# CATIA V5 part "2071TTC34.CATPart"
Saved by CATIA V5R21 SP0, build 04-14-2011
Part number: 2071TTC34
Bounding box of the stored display mesh (mm): x -14 to 14, y 0 to 1000, z -22.5 to 18.5
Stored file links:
  C:\Users\ALI OZGUN\Desktop\alhan\PROFILLER\2071TTC34.CATPart
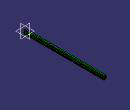
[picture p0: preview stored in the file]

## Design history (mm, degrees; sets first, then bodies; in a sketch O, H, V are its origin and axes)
Body1 (main body)
  Sketch1 on zx-plane, origin (0, 0, 0), H (-1, 0, 0), V (0, 0, 1)
    line L1 (14, 15.9) -> (14, -18.5)
    line L2 (14, -18.5) -> (-14, -18.5)
    line L3 (-14, -18.5) -> (-14, -3.1)
    line L4 (-14, 18.5) -> (-2.7, 18.5)
    point P4 (-14, 3)
    line L5 (-2.7, -3.1) -> (-14, -3.1)
    line L6 (-14, 9.1) -> (-2.7, 9.1)
    point P5 (-9.0936, 12.527)
    point P6 (0.5, 3)
    line L7 (3.7, 11.5) -> (3.7, -5.5)
    line L8 (3.7, -5.5) -> (-2.7, -5.5)
    line L9 (-2.7, -5.5) -> (-2.7, -3.1)
    line L10 (-2.7, 11.5) -> (3.7, 11.5)
    line L11 (14, 15.9) -> (-2.7, 15.9)
    line L12 (-2.7, 15.9) -> (-2.7, 18.5)
    axis line L13 (-44.5224, 3) -> (23.1973, 3)
    line L14 (-14, 9.1) -> (-14, 18.5)
    point P18 (-2.7, 9.1)
    line L15 (-2.7, 9.1) -> (-2.7, 11.5)
    distance L6 L5 = 12.2
    distance L10 L8 = 17
    distance L7 L9 = 6.4
    distance L12 L3 = 11.3
    distance L1 L3 = 28
    distance L4 L2 = 37
    distance L13 L2 = 21.5
    distance L11 L4 = 2.6
    vertical: L1 V, L3 V, L7 V, L9 V, L12 V, L14 V, L15 V
    horizontal: L2 H, L4 H, L5 H, L6 H, L8 H, L10 H, L11 H, L13 H
    equidistance: L1 L3 O, L2 L4 O, L5 L6 P4, L7 L9 P6, L8 L10 P6
    coincidence: P4 L3, L9 L12, L3 L14, L9 P18, L9 L15
    symmetry: L6 L5 L13, L8 L10 L13
  Pad1: profile Sketch1, direction (0, 1, 0), length 1000
  Body2
    Solid1: linked copy from another document
  Remove1: tool Body2
  RemoveFace1: RemoveFaces (face of Solid1; face of Solid1)
Body3
  Sketch2 on start face of Pad1, origin (0, 0, 0), H (1, 0, 0), V (0, 0, 1)
    point P1 (0, -16.5)
    line L1 (14, -11.5) -> (14, -21.5)
    line L2 (13, -22.5) -> (-13, -22.5)
    line L3 (-14, -21.5) -> (-14, -11.5)
    line L4 (7, -10.5) -> (13, -10.5)
    point P2 (-14, -10.5)
    point P3 (7, -10.5)
    line L5 (-13, -10.5) -> (-7, -10.5)
    point P4 (-7, -10.5)
    reference projected line E1 (2.7, 18.5) -> (14, 18.5) from edge [start face of Pad1 | face of Pad1 from Sketch1.L4]
    arc A1 centre (13, -11.5) radius 1 from (14, -11.5) to (13, -10.5) ccw
    arc A2 centre (13, -21.5) radius 1 from (14, -21.5) to (13, -22.5) cw
    arc A3 centre (-13, -21.5) radius 1 from (-13, -22.5) to (-14, -21.5) cw
    arc A4 centre (-13, -11.5) radius 1 from (-14, -11.5) to (-13, -10.5) cw
    distance P3 P4 = 14
    distance L1 L3 = 28
    distance L4 L2 = 12
    distance L2 E1 = 41
    radius A1 = 1
    radius A2 = 1 {= Sketch2.radius(A1)}
    radius A3 = 1 {= Sketch2.radius(A1)}
    radius A4 = 1 {= Sketch2.radius(A1)}
    coincidence: P1 V, P2 L4, L3 P2, L5 P2
    vertical: L1 V, L3 V
    horizontal: L2 H, L4 H, L5 H
    equidistance: L1 L3 P1, L2 L4 P1
    symmetry: P4 P3 V
    tangency: A1 L1, A1 L4, A2 L1, A2 L2, A3 L2, A3 L3, A4 L3, A4 L5
  Pad2: profile Sketch2, direction (0, 1, 0), length 1000, thin wall 1.5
